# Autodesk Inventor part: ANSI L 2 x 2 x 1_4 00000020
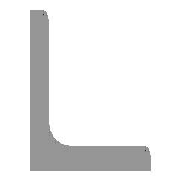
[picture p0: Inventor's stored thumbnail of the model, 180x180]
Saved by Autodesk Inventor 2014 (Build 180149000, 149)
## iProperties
IsCustomPart: 1
Created: 2007-02
Part Number: ANSI L 2 x 2 x 1_4 00000020
Material: Steel, Mild
Document SubType Name: Modeling
Standard: AISC
Designer: Autodesk, Inc.
Size Designation: L 2 x 2 x 1/4
Stock Number: L 2 x 2 x 1/4
Density: 7.86 g/cm^3
Description: Angle Steel
Standards Organization: ANSI
Language: en-US
Categories: <MemberInstance><Categories><Category DisplayName="Structural Shapes" InternalName="089c4875-fa83-4c05-b084-43b9cc11f5ed" Mnemonic="GRDR"><CategoryParameter Dis
Mass: 3340.3 g
Surface Area: 1393.58 cm^2
Volume: 424.975 cm^3
Appearance: Steel
_FrameMemberDoc: Frame Member File
_Version: 15.0.0
_CCFamilyMember: 11
_CCFamilyDisplayName: ANSI L (Equal angles) - Angle Steel
G_L: 28.675 in
G_W: 2.000 in
G_H: 2.000 in
+575F4D84-8C58-4D54-B597-150D11212010+CUTDETAIL1: Cut
+04565ACE-EC82-46BC-A997-561150C5DCC6+CUTDETAIL2: Cut
+3B63BCEE-D16C-47A0-9931-D23DE30D7179+CUTDETAIL3: Notch
Author: Autodesk, Inc.
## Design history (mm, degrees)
node "Start plane"
node "End plane"
sketch "Sketch"
  geometry: L1 (50.8, 0)-(0, 0); L2 (0, 0)-(0, 50.8); L3 (0, 50.8)-(3.302, 50.8); L4 (6.35, 47.752)-(6.35, 12.7); L5 (12.7, 6.35)-(47.752, 6.35); L6 (50.8, 3.302)-(50.8, 0); L7 (0, -11.041)-(0, 31.538); L8 (-11.041, 0)-(31.538, 0); L9 (0, 63.926)-(0, -23.536) reference; L10 (-23.536, 0)-(63.926, 0) reference; A1 r 6.35 centre (12.7, 12.7) between (6.35, 12.7) and (12.7, 6.35); A2 r 3.048 centre (3.302, 47.752) between (6.35, 47.752) and (3.302, 50.8); A3 r 3.048 centre (47.752, 3.302) between (50.8, 3.302) and (47.752, 6.35); 3 further points
  constraints: 16 end point, 6 point on circle, 6 point on line, 6 tangent, 4 parallel, 3 centre point, 2 collinear, 1 equal radius, 1 horizontal, 1 perpendicular
  dimensions: "d0" = 50.8 distance between parallel lines of L6 L2 (= G_H); "d1" = 50.8 distance between parallel lines of L3 L1 (= G_H); "d2" = 6.35 distance between parallel lines of L2 L4 (= G_T); "d3" = 6.35 distance between parallel lines of L1 L5 (= G_T); "d10" = 0 distance between parallel lines of L7 L2 (computed from ex); "d11" = 0 distance between parallel lines of L8 L1 (computed from d10); "d14" = 6.35 radius of A1 (= G_IR); "d15" = 3.048 radius of A2 (= G_ER)
extrude "Body" new body sketch "Sketch" stored distance "d4" = 728.33422 (= G_L); taper "d5" = 0 deg
node "Driven Length"
  sketch "Sketch4"
    geometry: L1 (0, 0)-(10, 0) reference
    constraints: 2 end point, 1 horizontal
  workplane "Work Plane7"
  sketch "Sketch5"
    geometry: L1 (-2, -5.542)-(12, -5.542) reference; L2 (-2, 722.793)-(12, 722.793) reference
    dimensions: "d19" = 728.33422 distance between parallel lines of L1 L2 (derived)
workplane "Work Plane3"
split "Split1"
workplane "Work Plane4"
split "Split2"
workplane "Work Plane5"
workplane "Work Plane6"
workplane "Work Plane8"
body "Solid1"
sketch "Sketch_1"
  geometry: L1 (50.8, 0)-(0, 0); L2 (0, 0)-(0, 50.8); L3 (0, 50.8)-(3.302, 50.8); L4 (6.35, 47.752)-(6.35, 12.7); L5 (12.7, 6.35)-(47.752, 6.35); L6 (50.8, 3.302)-(50.8, 0); A1 r 3.048 centre (3.302, 47.752) between (6.35, 47.752) and (3.302, 50.8); A2 r 6.35 centre (12.7, 12.7) between (6.35, 12.7) and (12.7, 6.35); A3 r 3.048 centre (47.752, 3.302) between (50.8, 3.302) and (47.752, 6.35)
  constraints: 12 end point, 6 point on circle, 3 centre point
extrude "Extrusion2" cut sketch "Sketch_1" stored distance "d20" = 3.302; taper "d21" = 0 deg
other parameters: "G_H" = 50.8 [user parameter; used in 2 equation terms], "G_T" = 6.35 [user parameter; used in 2 equation terms], "G_ER" = 3.048 [user parameter; used in 1 equation term], "G_IR" = 6.35 [user parameter; used in 1 equation term], "G_L" = 728.33422 (= d19) [user parameter; used in 1 equation term], "ex" = 0 [user parameter; used in 1 equation term], "G_OFFSET_START" = 5.54156 [user parameter; used in 1 equation term], "G_OFFSET_END" = -13.49265 [user parameter; used in 1 equation term], "d12" = -5.54156 (= -G_OFFSET_START), "d13" = 722.79265 (= G_OFFSET_END + B_L), "B_L" = 736.2853 [user parameter; used in 1 equation term], "d18" = 90 deg
